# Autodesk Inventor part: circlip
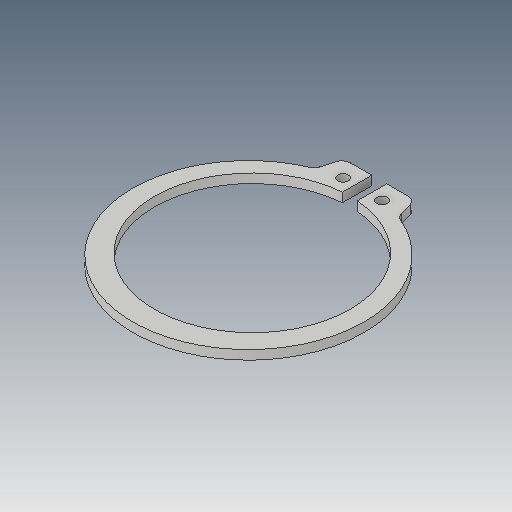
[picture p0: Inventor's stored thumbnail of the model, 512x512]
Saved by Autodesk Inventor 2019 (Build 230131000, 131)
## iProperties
Created: 2016-06
Part Number: circlip
Material: Generic
Document SubType Name: Modeling
Designer: CADCIM
Density: 1 g/cm^3
Appearance: Default
Author: CADCIM
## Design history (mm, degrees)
sketch "Sketch1"
  geometry: L1 (9.52, -25.305)-(8.665, -28.284); L2 (6.743, -29.733)-(1.75, -29.733); L3 (1.75, -29.733)-(1.75, -22.833); L4 (0, 0)-(0, -33.55); L5 (-6.743, -29.733)-(-1.75, -29.733); L6 (-1.75, -29.733)-(-1.75, -22.833); L7 (-9.52, -25.305)-(-8.665, -28.284); C1 r 1.25 at (4.55, -25.815); C2 r 1.25 at (-4.55, -25.815); A1 r 22.9 centre (0, 0) between (1.75, -22.833) and (-1.75, -22.833); A2 r 27.1 centre (0, 0.9) between (10.656, -24.017) and (-10.656, -24.017); A3 r 2 centre (-6.743, -27.733) between (-8.665, -28.284) and (-6.743, -29.733); A4 r 2 centre (-11.442, -25.856) between (-9.52, -25.305) and (-10.656, -24.017); A5 r 2 centre (11.442, -25.856) between (10.656, -24.017) and (9.52, -25.305); A6 r 2 centre (6.743, -27.733) between (6.743, -29.733) and (8.665, -28.284); 12 further points
  constraints: 18 point on circle, 14 end point, 8 centre point, 8 point on line, 8 tangent, 4 equal radius, 4 symmetric about line, 2 coincident, 2 midpoint, 1 horizontal, 1 horizontal alignment, 1 perpendicular, 1 vertical
  dimensions: "d0" = 45.8 diameter of A1; "d4" = 6.9 distance from line of L6.end L5; "d5" = 5.1 distance of point (0, 28) point (0, 22.9); "d6" = 2.5 diameter of C1; "d8" = 2 radius of A3 (derived); "d9" = 2.8 distance from line of C1.centre L3; "d10" = 3.5 distance of L5.end L2.end; "d11" = 27.1 radius of A2; "d14" = 6.5 distance of L5.end point (-8.25, -29.733); "d15" = 32 deg angle of L7 L1
extrude "Extrusion1" new body sketch "Sketch1" distance "d16" = 2.15; taper "d17" = 0 deg
body "Solid1"
other parameters: "d18" = 0
